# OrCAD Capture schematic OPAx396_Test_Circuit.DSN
size A; title: OPA396 Precision, Low IQ, Low Input Bias Current Op Amp; rev: 1.1; note: Datasheet: SBOSA65 EVM: N/A
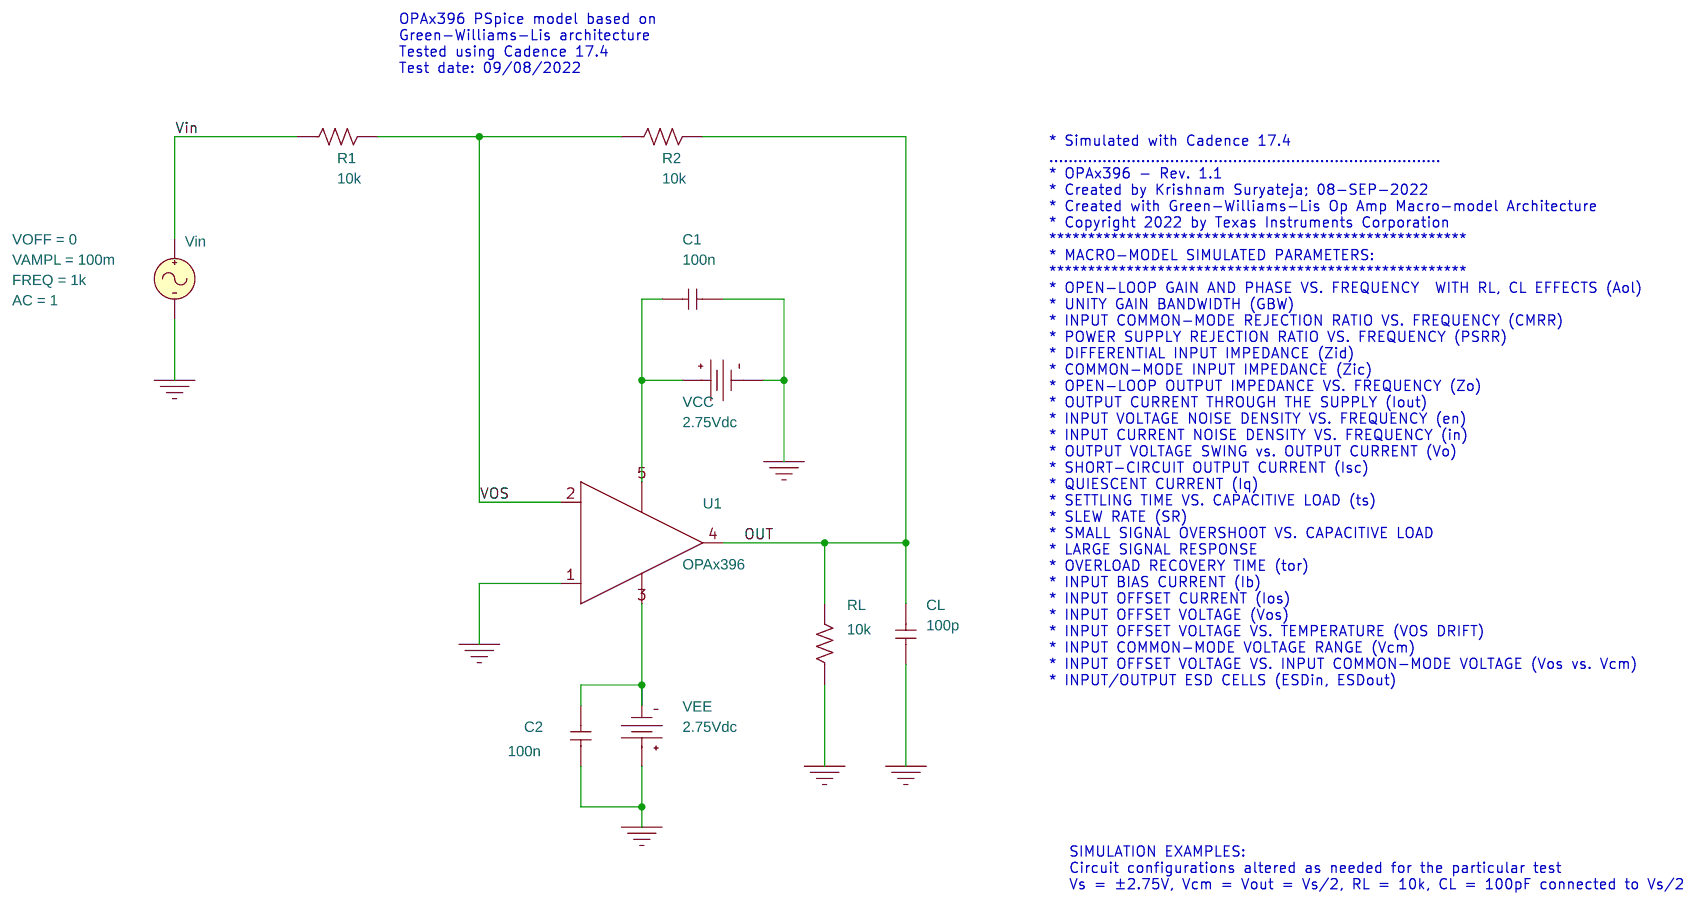
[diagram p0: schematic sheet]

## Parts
C1  100n  [cap196]
C2  100n  [cap196]
CL  100p  [RAD/CK05]
R1  10k  [AXRC05]
R2  10k  [AXRC05]
RL  10k  [AXRC05]
U1  OPAx396
VCC  VDC
VEE  VDC
Vin  VSIN

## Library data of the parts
C1 C2 CL = C
R1 R2 RL = R
U1 = OPAx396
VCC VEE = VDC: DC: 2.75Vdc
Vin = VSIN: AC: 1; FREQ: 1k; VAMPL: 100m; VOFF: 0

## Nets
Vin: R1.1 Vin.1(+)
0: C1.2 C2.1 CL.1 RL.1 U1.1(+) VCC.1(-) VEE.0(+) Vin.2(-)
OUT: CL.2 R2.2 RL.2 U1.4(OUT)
VOS: R1.2 R2.1 U1.2(-)
N27303: C1.1 U1.5(V+) VCC.0(+)
N27354: C2.2 U1.3(V-) VEE.1(-)

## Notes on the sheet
- OPAx396 PSpice model based on
  Green-Williams-Lis architecture
  Tested using Cadence 17.4
  Test date: 09/08/2022
- * Simulated with Cadence 17.4
  .................................................................................
  * OPAx396 - Rev. 1.1
  * Created by Krishnam Suryateja; 08-SEP-2022
  * Created with Green-Williams-Lis Op Amp Macro-model Architecture
  * Copyright 2022 by Texas Instruments Corporation
  ******************************************************
  * MACRO-MODEL SIMULATED PARAMETERS:
  ******************************************************
  * OPEN-LOOP GAIN AND PHASE VS. FREQUENCY  WITH RL, CL EFFECTS (Aol)
  * UNITY GAIN BANDWIDTH (GBW)
  * INPUT COMMON-MODE REJECTION RATIO VS. FREQUENCY (CMRR)
  * POWER SUPPLY REJECTION RATIO VS. FREQUENCY (PSRR)
  * DIFFERENTIAL INPUT IMPEDANCE (Zid)
  * COMMON-MODE INPUT IMPEDANCE (Zic)
  * OPEN-LOOP OUTPUT IMPEDANCE VS. FREQUENCY (Zo)
  * OUTPUT CURRENT THROUGH THE SUPPLY (Iout)
  * INPUT VOLTAGE NOISE DENSITY VS. FREQUENCY (en)
  * INPUT CURRENT NOISE DENSITY VS. FREQUENCY (in)
  * OUTPUT VOLTAGE SWING vs. OUTPUT CURRENT (Vo)
  * SHORT-CIRCUIT OUTPUT CURRENT (Isc)
  * QUIESCENT CURRENT (Iq)
  * SETTLING TIME VS. CAPACITIVE LOAD (ts)
  * SLEW RATE (SR)
  * SMALL SIGNAL OVERSHOOT VS. CAPACITIVE LOAD
  * LARGE SIGNAL RESPONSE
  * OVERLOAD RECOVERY TIME (tor)
  * INPUT BIAS CURRENT (Ib)
  * INPUT OFFSET CURRENT (Ios)
  * INPUT OFFSET VOLTAGE (Vos)
  * INPUT OFFSET VOLTAGE VS. TEMPERATURE (VOS DRIFT)
  * INPUT COMMON-MODE VOLTAGE RANGE (Vcm)
  * INPUT OFFSET VOLTAGE VS. INPUT COMMON-MODE VOLTAGE (Vos vs. Vcm)
  * INPUT/OUTPUT ESD CELLS (ESDin, ESDout)
- SIMULATION EXAMPLES:
  Circuit configurations altered as needed for the particular test
  Vs = ±2.75V, Vcm = Vout = Vs/2, RL = 10k, CL = 100pF connected to Vs/2
